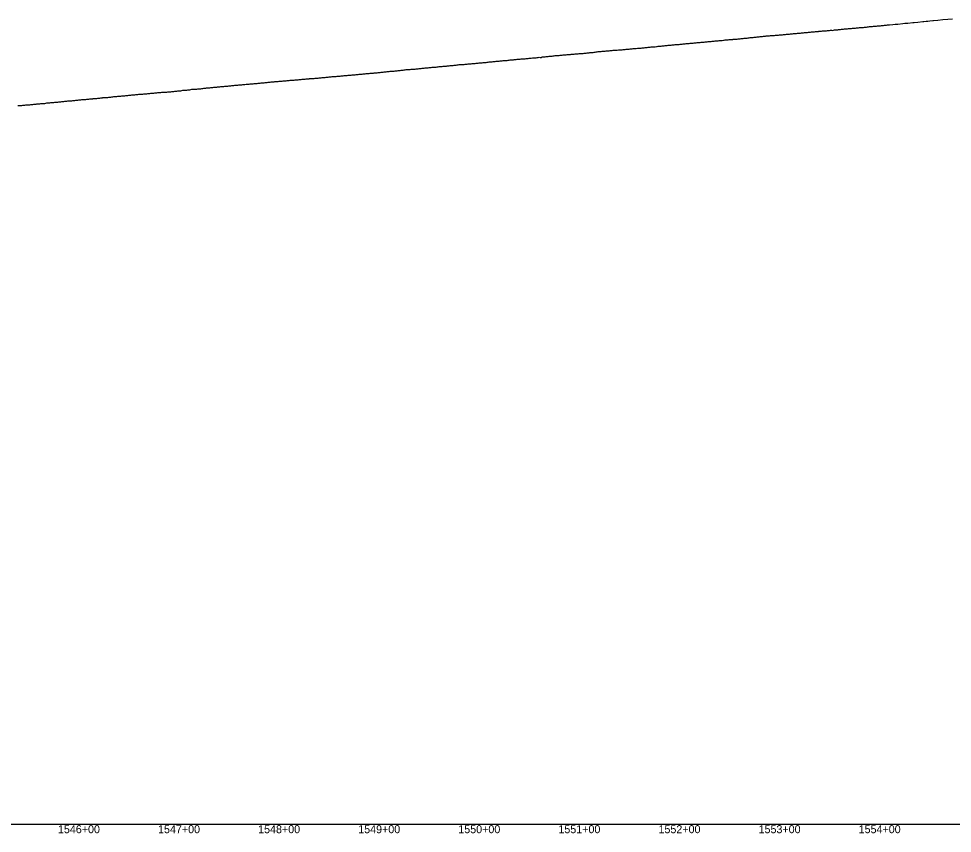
# Model space of a CAD drawing. Extents: x -3793 to 50787, y -1075 to 6138.
# Drawn here: x 41858 to 42791, y 2991 to 3805 of the extents above; entities that cross this region are included whole.
import ezdxf

# ---------------------------------------------------------------- set-up
doc = ezdxf.new("R2010")
doc.units = 0
for name, color, linetype in [('RD_DDB_Profile_EX', 7, 'Continuous'), ('RD_DDB_StaTX', 7, 'Continuous'), ('RD_GPK_Profile_Cell', 7, 'Continuous')]:
    doc.layers.add(name, color=color, linetype=linetype)

msp = doc.modelspace()

# ---------------------------------------------------------------- linework, layer by layer
at = {"layer": 'RD_DDB_Profile_EX'}
for points in [[(42639.398531, 3790.06941), (42640.398902, 3790.3162), (42641.389983, 3790.3676), (42642.390352, 3790.51824), (42643.39123, 3790.666715), (42644.391599, 3790.716415), (42645.391977, 3790.71897), (42646.392354, 3790.81863), (42647.393224, 3790.967175), (42648.3936, 3791.018735), (42649.393781, 3791.069245), (42650.394139, 3791.217005), (42651.394506, 3791.413995), (42652.395368, 3791.466995), (42653.385912, 3791.517495), (42654.386275, 3791.615375), (42655.386637, 3791.71417), (42656.386999, 3791.765445), (42657.387857, 3791.86498), (42657.80875, 3791.88586), (42658.388211, 3791.914575), (42659.388402, 3792.063355), (42660.388747, 3792.162935), (42661.389597, 3792.263995), (42662.389949, 3792.31356), (42663.390294, 3792.36457), (42664.390645, 3792.414085), (42665.390996, 3792.51292), (42666.391847, 3792.61254), (42667.382337, 3792.66212), (42668.38267, 3792.810975), (42669.383002, 3792.90988), (42670.38321, 3792.911195), (42671.384049, 3792.86386), (42672.384387, 3793.210345), (42673.384718, 3793.259285), (42674.385054, 3793.30933), (42675.38539, 3793.409315), (42676.386229, 3793.50957), (42676.882788, 3793.53412), (42677.386554, 3793.55994), (42678.386878, 3793.65928), (42679.387119, 3793.758615), (42680.378037, 3793.958005), (42681.378865, 3794.05776), (42682.379693, 3794.157935), (42683.380517, 3794.257655), (42684.381345, 3794.35828), (42685.382173, 3794.45799), (42686.419807, 3794.51328), (42687.383814, 3794.60923), (42688.384632, 3794.66033), (42689.385444, 3794.710455), (42690.376273, 3794.859105), (42691.37709, 3794.958705), (42692.377902, 3794.961915), (42693.378217, 3795.010625), (42694.379034, 3795.1593), (42695.379846, 3795.2104), (42695.956826, 3795.268125), (42696.380659, 3795.3105), (42697.381467, 3795.510055), (42698.382269, 3795.660105), (42699.383076, 3795.66016), (42700.383883, 3795.66124), (42701.3748, 3795.76133), (42702.375505, 3795.86139), (42703.376312, 3796.01041), (42704.377114, 3796.06203), (42705.493845, 3796.185265), (42706.37872, 3796.361035), (42707.379513, 3796.411015), (42708.380311, 3796.560475), (42709.381109, 3796.660465), (42710.381902, 3796.71044), (42711.372712, 3796.860985), (42712.37351, 3796.96045), (42713.374303, 3797.108865), (42714.374601, 3797.157675), (42715.030864, 3797.15767), (42715.375391, 3797.15955), (42716.376181, 3797.20994), (42717.376971, 3797.358915), (42718.377756, 3797.458365), (42719.378545, 3797.509675), (42720.369439, 3797.70871), (42721.370223, 3797.709075), (42722.370922, 3797.808995), (42723.371712, 3797.95936), (42724.567883, 3798.07877), (42725.373281, 3798.15912), (42726.374064, 3798.208965), (42727.374842, 3798.35838), (42728.406739, 3798.361955), (42731.771588, 3798.7585), (42734.104902, 3798.94505), (42736.765233, 3799.157925), (42741.768633, 3799.70673), (42743.641921, 3799.87542), (42746.762838, 3800.15652), (42751.756204, 3800.654475)], [(42751.756204, 3800.654475), (42753.178941, 3800.782005), (42756.75934, 3801.102695), (42761.75249, 3801.65084), (42762.71596, 3801.72766), (42765.040757, 3801.91286), (42766.758587, 3802.049645), (42768.608844, 3802.23539), (42771.752606, 3802.550805), (42772.252979, 3802.60109), (42776.749585, 3803.05263), (42781.789998, 3803.60834), (42786.753317, 3804.105235), (42791.327017, 3804.518305)], [(42543.411697, 3781.210655), (42544.412235, 3781.311575), (42545.412271, 3781.46052), (42546.412301, 3781.5101), (42547.412331, 3781.559675), (42548.412875, 3781.65996), (42549.412905, 3781.7601), (42550.412834, 3781.8602), (42551.412868, 3781.959215), (42552.413404, 3782.05951), (42552.90154, 3782.13251), (42553.413434, 3782.208535), (42554.413448, 3782.258055), (42555.413462, 3782.407575), (42556.413983, 3782.4578), (42557.413998, 3782.55732), (42558.414012, 3782.70684), (42559.41403, 3782.806365), (42560.404635, 3782.75738), (42561.404644, 3782.8572), (42562.438559, 3783.06171), (42563.405157, 3783.20547), (42564.40566, 3783.305275), (42565.40616, 3783.355415), (42566.406659, 3783.4063), (42567.407162, 3783.505705), (42568.407583, 3783.605455), (42569.408085, 3783.60719), (42570.408084, 3783.60773), (42571.408585, 3783.856425), (42571.975578, 3783.884855), (42572.409078, 3783.906565), (42573.409561, 3783.95667), (42574.410043, 3784.00678), (42575.410522, 3784.107285), (42576.401097, 3784.108245), (42577.401071, 3784.256795), (42578.401554, 3784.45614), (42579.402038, 3784.50663), (42580.402522, 3784.60634), (42581.512597, 3784.718615), (42582.403472, 3784.80771), (42583.403937, 3784.95695), (42584.403818, 3785.0563), (42585.404282, 3785.107095), (42586.404747, 3785.207145), (42587.405211, 3785.25682), (42588.405675, 3785.406875), (42589.406136, 3785.55692), (42590.406098, 3785.65623), (42591.049617, 3785.688425), (42591.406556, 3785.706955), (42592.397083, 3785.75697), (42593.39753, 3785.956955), (42594.397977, 3786.056595), (42595.398424, 3786.106585), (42596.398871, 3786.35588), (42597.398806, 3786.40578), (42598.399253, 3786.50577), (42599.399639, 3786.655455), (42600.586636, 3786.746115), (42601.40052, 3786.70598), (42602.40095, 3786.905015), (42603.40188, 3787.05597), (42604.402812, 3787.20627), (42605.393326, 3787.305855), (42606.394265, 3787.405645), (42607.395203, 3787.40704), (42608.395633, 3787.50654), (42609.396575, 3787.656625), (42610.397, 3787.65749), (42611.397926, 3787.708035), (42612.398846, 3787.808565), (42613.399159, 3787.85951), (42614.400072, 3788.008425), (42615.40099, 3788.058935), (42616.401405, 3788.16), (42617.392459, 3788.16184), (42618.393378, 3788.310505), (42619.660674, 3788.361195), (42620.394704, 3788.361565), (42621.395613, 3788.4635), (42622.396011, 3788.661895), (42623.39692, 3788.71241), (42624.397821, 3788.812155), (42625.398226, 3788.91199), (42626.398972, 3789.013245), (42627.399874, 3789.11457), (42628.400274, 3789.164375), (42629.401174, 3789.265735), (42630.392236, 3789.362835), (42631.392627, 3789.465995), (42632.393512, 3789.565625), (42633.394405, 3789.665215), (42634.394788, 3789.71585), (42635.395681, 3789.76724), (42636.396565, 3789.916805), (42637.396773, 3789.96748), (42638.397652, 3789.970815), (42638.734712, 3790.00469), (42639.398531, 3790.06941)], [(42447.435848, 3772.504305), (42447.994331, 3772.532315), (42448.436142, 3772.555145), (42449.436919, 3772.65629), (42450.437198, 3772.70645), (42451.437474, 3772.80619), (42452.437753, 3772.90634), (42453.438028, 3772.956485), (42454.438308, 3773.006635), (42455.439085, 3773.05788), (42456.439365, 3773.158545), (42457.53135, 3773.27249), (42458.439792, 3773.407785), (42459.430152, 3773.45789), (42460.430405, 3773.508525), (42461.431155, 3773.56159), (42462.43141, 3773.661725), (42463.431658, 3773.760665), (42464.431912, 3773.85959), (42465.43216, 3774.0109), (42466.432415, 3774.06041), (42467.068369, 3774.124465), (42467.433155, 3774.160525), (42468.433383, 3774.21124), (42469.433605, 3774.31129), (42470.433834, 3774.36268), (42471.434055, 3774.462065), (42472.434284, 3774.61145), (42473.435008, 3774.66219), (42474.435237, 3774.712245), (42475.435458, 3774.81157), (42476.605388, 3774.920115), (42477.435887, 3774.96308), (42478.43644, 3775.063045), (42479.436635, 3775.163035), (42480.436839, 3775.214565), (42481.427196, 3775.26534), (42482.4274, 3775.364575), (42483.427595, 3775.51456), (42484.428302, 3775.66372), (42485.428497, 3775.714515), (42486.428694, 3775.81611), (42487.428864, 3775.91523), (42488.429042, 3775.965165), (42489.429212, 3776.11509), (42490.429894, 3776.264965), (42491.430064, 3776.31572), (42492.430243, 3776.41648), (42493.430413, 3776.46558), (42494.430583, 3776.565505), (42495.679426, 3776.740645), (42496.421425, 3776.81695), (42497.42157, 3776.96512), (42498.421724, 3777.065), (42499.421869, 3777.11569), (42500.422518, 3777.21632), (42501.422672, 3777.362785), (42502.422817, 3777.46267), (42503.422971, 3777.514245), (42504.42362, 3777.66481), (42505.42376, 3777.76467), (42506.42389, 3777.81535), (42507.424011, 3777.96347), (42508.424635, 3778.014815), (42509.424765, 3778.11464), (42510.424716, 3778.214455), (42511.424839, 3778.26595), (42512.425467, 3778.36566), (42513.42559, 3778.4646), (42514.425721, 3778.61273), (42514.753464, 3778.64545), (42515.425829, 3778.71253), (42516.426425, 3778.71551), (42517.416713, 3778.71698), (42518.41681, 3778.866695), (42519.416907, 3779.014765), (42520.417518, 3779.16271), (42521.417615, 3779.21166), (42522.417712, 3779.313915), (42523.417817, 3779.41529), (42524.418417, 3779.51412), (42525.418491, 3779.613005), (42526.418573, 3779.76273), (42527.418648, 3779.763225), (42528.419075, 3779.864425), (42529.419153, 3779.96332), (42530.419231, 3779.96455), (42531.419316, 3779.964225), (42532.419891, 3780.113885), (42533.419969, 3780.262815), (42533.827502, 3780.283065), (42534.420042, 3780.31322), (42535.420097, 3780.462125), (42536.420652, 3780.563185), (42537.420715, 3780.613525), (42538.410919, 3780.66314), (42539.410978, 3780.812075), (42540.411536, 3780.961045), (42541.411588, 3781.012045), (42542.411646, 3781.11167), (42543.411697, 3781.210655)], [(42356.455189, 3763.951945), (42357.455268, 3764.001985), (42358.454832, 3764.05169), (42359.454911, 3764.151645), (42360.454476, 3764.25087), (42361.454555, 3764.300975), (42362.454109, 3764.300405), (42363.454153, 3764.400375), (42363.946038, 3764.424605), (42364.454343, 3764.44962), (42365.454401, 3764.599605), (42366.454463, 3764.699595), (42367.455284, 3764.848775), (42368.455346, 3764.998835), (42369.456165, 3765.09797), (42370.456227, 3765.198075), (42371.698178, 3765.272365), (42372.454061, 3765.34789), (42373.455783, 3765.44875), (42374.455917, 3765.448765), (42375.454322, 3765.54853), (42376.455426, 3765.699245), (42377.45556, 3765.79918), (42378.444594, 3765.9989), (42379.445064, 3765.899765), (42380.445199, 3765.89976), (42381.444849, 3766.2995), (42382.143434, 3766.36985), (42382.445106, 3766.400175), (42383.445083, 3766.45005), (42383.812663, 3766.48676), (42384.584561, 3766.563945), (42385.44555, 3766.650465), (42386.445527, 3766.75039), (42387.445504, 3766.90024), (42388.445994, 3767.000865), (42389.445971, 3767.05073), (42390.445948, 3767.100595), (42390.772216, 3767.1171), (42391.446415, 3767.15136), (42392.44636, 3767.40086), (42393.446816, 3767.45143), (42394.446761, 3767.601245), (42395.446706, 3767.70106), (42396.447161, 3767.701665), (42397.447106, 3767.80139), (42398.447051, 3767.901205), (42399.447506, 3768.001615), (42400.447446, 3767.951705), (42401.447345, 3768.05151), (42402.447762, 3768.301635), (42403.44768, 3768.351585), (42404.447596, 3768.451325), (42405.448014, 3768.55161), (42406.44793, 3768.65138), (42407.447847, 3768.80108), (42408.448265, 3768.80168), (42409.448181, 3768.801605), (42409.846254, 3768.86182), (42410.438099, 3768.951235), (42411.438492, 3769.051655), (42412.438374, 3769.05134), (42413.438257, 3769.200965), (42414.43865, 3769.25136), (42415.438532, 3769.300995), (42416.438415, 3769.350935), (42417.438807, 3769.451495), (42418.43869, 3769.700905), (42419.439081, 3769.751175), (42420.438934, 3769.80089), (42421.438786, 3769.90053), (42422.439148, 3769.901075), (42423.439001, 3770.10057), (42424.438854, 3770.20016), (42425.439216, 3770.150605), (42426.439069, 3770.400125), (42426.809814, 3770.43708), (42427.43905, 3770.49972), (42428.104581, 3770.53327), (42428.439284, 3770.550115), (42428.920293, 3770.598035), (42429.439278, 3770.649655), (42430.439338, 3770.79905), (42431.439511, 3770.79951), (42431.859744, 3770.84201), (42432.440119, 3770.9006), (42433.44045, 3771.050895), (42434.440782, 3771.15119), (42435.441113, 3771.251405), (42436.441444, 3771.451485), (42437.432317, 3771.602195), (42438.457312, 3771.60507), (42439.432917, 3771.70279), (42440.433219, 3771.852985), (42441.433522, 3772.002755), (42442.433826, 3772.003375), (42443.434632, 3772.004735), (42444.434937, 3772.10496), (42445.43524, 3772.25488), (42446.435545, 3772.35509), (42447.435848, 3772.504305)], [(42261.487296, 3754.958555), (42262.487251, 3755.058055), (42263.487704, 3755.257835), (42264.487655, 3755.35777), (42265.487611, 3755.407255), (42266.487562, 3755.408085), (42266.790969, 3755.423235), (42267.487485, 3755.458855), (42268.487395, 3755.6574), (42269.477396, 3755.70771), (42270.477814, 3755.80693), (42271.477723, 3755.95545), (42272.477636, 3756.00671), (42273.477545, 3756.107475), (42274.477454, 3756.15735), (42275.477362, 3756.257645), (42276.477269, 3756.406675), (42277.477137, 3756.555685), (42278.477515, 3756.65611), (42279.477387, 3756.706385), (42280.477254, 3756.756635), (42281.477122, 3756.85646), (42282.476915, 3756.957075), (42283.476785, 3757.106495), (42284.476654, 3757.15631), (42285.476524, 3757.206125), (42285.865007, 3757.22574), (42286.476876, 3757.256605), (42287.476706, 3757.356735), (42288.476536, 3757.456475), (42289.476369, 3757.655185), (42290.476199, 3757.70497), (42291.476029, 3757.85475), (42292.476363, 3757.9055), (42293.4767, 3758.05556), (42294.47653, 3758.1557), (42295.47686, 3758.20651), (42296.476655, 3758.256575), (42297.476948, 3758.456215), (42298.47674, 3758.60519), (42299.477037, 3758.60552), (42300.476828, 3758.6564), (42301.477122, 3758.806795), (42302.467502, 3758.857195), (42303.467294, 3758.906895), (42304.467592, 3758.95729), (42304.939045, 3759.004305), (42305.467359, 3759.05696), (42306.467622, 3759.1573), (42307.467371, 3759.355715), (42308.46763, 3759.406845), (42309.467888, 3759.50716), (42310.467642, 3759.55683), (42311.4679, 3759.657145), (42312.467649, 3759.75723), (42313.467912, 3759.857125), (42314.476064, 3759.907625), (42315.467882, 3760.007485), (42316.467598, 3760.10707), (42317.467818, 3760.10778), (42318.468037, 3760.258525), (42319.467749, 3760.35763), (42320.467973, 3760.40837), (42321.467685, 3760.40832), (42322.467905, 3760.706915), (42323.467621, 3760.756935), (42324.013083, 3760.784355), (42324.467828, 3760.80761), (42325.468011, 3760.90828), (42326.467608, 3761.05653), (42327.467792, 3761.15674), (42328.467476, 3761.25708), (42329.467656, 3761.30772), (42330.46734, 3761.456435), (42331.467525, 3761.55666), (42332.467208, 3761.656185), (42333.550102, 3761.764315), (42334.46754, 3761.85619), (42335.467187, 3762.005685), (42336.467336, 3761.95694), (42337.466979, 3762.15567), (42338.467128, 3762.205835), (42339.466774, 3762.35468), (42340.466923, 3762.35547), (42341.467068, 3762.50563), (42342.456778, 3762.605105), (42343.087121, 3762.668235), (42343.456915, 3762.70525), (42344.456519, 3762.705205), (42345.45663, 3762.75532), (42346.456234, 3762.904655), (42347.456348, 3763.05402), (42348.455951, 3763.15303), (42349.456063, 3763.30356), (42350.456177, 3763.35389), (42351.45578, 3763.4533), (42352.62414, 3763.56172), (42353.455465, 3763.60276), (42354.455544, 3763.702645), (42355.45511, 3763.852025), (42356.455189, 3763.951945)], [(42166.504283, 3746.10456), (42167.504175, 3746.204355), (42168.50402, 3746.303925), (42169.504424, 3746.404235), (42170.504319, 3746.504285), (42171.504206, 3746.60408), (42172.504562, 3746.704575), (42173.504405, 3746.75431), (42174.504251, 3746.80428), (42175.504604, 3746.905045), (42176.504447, 3747.00428), (42177.50429, 3747.10424), (42178.504641, 3747.204255), (42179.504484, 3747.20424), (42180.504837, 3747.354465), (42180.957797, 3747.42231), (42181.504652, 3747.503445), (42182.504448, 3747.504105), (42183.504752, 3747.60453), (42184.504546, 3747.803735), (42185.504343, 3747.85366), (42186.504647, 3747.90454), (42187.504441, 3747.954195), (42188.504238, 3748.05365), (42189.504542, 3748.104075), (42190.504336, 3748.203955), (42191.504086, 3748.30336), (42192.504343, 3748.403725), (42193.504094, 3748.40371), (42194.504348, 3748.45431), (42195.504099, 3748.60368), (42196.49388, 3748.653245), (42197.494139, 3748.753825), (42198.493886, 3748.953055), (42199.493633, 3748.95307), (42200.031835, 3749.007115), (42200.49387, 3749.053475), (42201.493571, 3749.252795), (42202.493272, 3749.352165), (42203.493485, 3749.40262), (42204.493186, 3749.5017), (42205.493376, 3749.601985), (42206.493082, 3749.65193), (42207.492789, 3749.65148), (42208.492999, 3749.901425), (42209.568854, 3749.95876), (42210.492372, 3750.050625), (42211.492538, 3750.10093), (42212.4922, 3750.20034), (42213.073745, 3750.258175), (42213.492224, 3750.299765), (42214.542514, 3750.4), (42215.492505, 3750.399495), (42215.982077, 3750.47351), (42216.492359, 3750.550555), (42217.492525, 3750.600855), (42218.49269, 3750.70113), (42219.105873, 3750.76261), (42219.492838, 3750.80138), (42220.49296, 3751.00136), (42221.493081, 3751.15145), (42222.493202, 3751.201805), (42223.493325, 3751.302095), (42224.493947, 3751.35311), (42225.494068, 3751.50314), (42226.494191, 3751.603325), (42227.494313, 3751.65351), (42228.642892, 3751.783605), (42229.49452, 3751.953625), (42230.494598, 3752.05374), (42231.494678, 3752.05407), (42232.495257, 3752.204705), (42233.485387, 3752.25562), (42234.485469, 3752.355485), (42235.485549, 3752.45561), (42236.485628, 3752.556025), (42237.48571, 3752.705575), (42238.485776, 3752.70657), (42239.485812, 3752.80663), (42240.486359, 3753.00691), (42241.486395, 3753.107315), (42242.486431, 3753.207025), (42243.48647, 3753.307445), (42244.486506, 3753.407505), (42245.48647, 3753.606485), (42246.486508, 3753.606905), (42247.71693, 3753.681555), (42248.487047, 3753.758555), (42249.487044, 3753.80855), (42250.487037, 3753.957725), (42251.487029, 3754.107715), (42252.487026, 3754.15771), (42253.487019, 3754.208105), (42254.487012, 3754.258495), (42255.48751, 3754.45891), (42256.487503, 3754.45934), (42257.487486, 3754.55887), (42258.487438, 3754.659225), (42259.487393, 3754.80915), (42260.487345, 3754.859065), (42261.487296, 3754.958555)], [(42071.530454, 3737.693085), (42072.530157, 3737.793285), (42073.530602, 3737.892555), (42074.531047, 3737.99247), (42075.531486, 3738.09207), (42076.050587, 3738.117805), (42076.531955, 3738.14201), (42077.531708, 3738.14352), (42078.532202, 3738.34236), (42079.522788, 3738.39231), (42080.52328, 3738.49147), (42081.52303, 3738.59188), (42082.523529, 3738.64144), (42083.524028, 3738.790545), (42084.524526, 3738.93961), (42085.587606, 3739.04004), (42086.524816, 3739.04094), (42087.525366, 3739.090955), (42088.525916, 3739.23944), (42089.525616, 3739.38875), (42090.526153, 3739.43927), (42091.526697, 3739.538195), (42092.526503, 3739.589095), (42093.526309, 3739.640485), (42094.526854, 3739.73947), (42095.124625, 3739.82935), (42095.526664, 3739.889245), (42096.526513, 3739.939515), (42097.526361, 3739.9903), (42098.52621, 3740.090065), (42099.526058, 3740.191305), (42100.525907, 3740.340145), (42101.525755, 3740.43861), (42102.526337, 3740.539835), (42103.526186, 3740.59012), (42104.661645, 3740.75401), (42105.525928, 3740.84063), (42106.525829, 3740.94128), (42107.525729, 3741.091055), (42108.52563, 3741.19127), (42109.525524, 3741.191895), (42110.526164, 3741.29081), (42111.526065, 3741.34145), (42112.525965, 3741.49123), (42113.525866, 3741.591035), (42114.198664, 3741.62483), (42114.525784, 3741.64163), (42115.515823, 3741.741365), (42116.515769, 3741.79113), (42117.515721, 3741.89204), (42118.515673, 3741.94255), (42119.516371, 3741.99183), (42120.516323, 3742.041155), (42121.516274, 3742.23972), (42122.516226, 3742.341055), (42123.735683, 3742.4026), (42124.516166, 3742.442055), (42125.516171, 3742.591365), (42126.516176, 3742.641435), (42127.516927, 3742.74094), (42128.516932, 3742.889775), (42129.516192, 3742.991275), (42130.51612, 3743.04171), (42131.515388, 3743.092755), (42132.515394, 3743.143135), (42133.514674, 3743.244115), (42134.514733, 3743.29464), (42135.514052, 3743.395475), (42136.514114, 3743.54478), (42137.513431, 3743.59593), (42138.513491, 3743.69592), (42139.512806, 3743.796845), (42140.512866, 3743.84683), (42141.51218, 3743.947655), (42142.809721, 3743.992565), (42143.512337, 3744.097785), (42144.511705, 3744.24853), (42145.511818, 3744.298505), (42146.511185, 3744.34929), (42147.511299, 3744.44916), (42148.51073, 3744.55004), (42149.045968, 3744.630285), (42149.561005, 3744.702515), (42150.511223, 3744.750645), (42151.511214, 3744.750605), (42152.511708, 3744.80138), (42153.511649, 3744.90123), (42154.512101, 3745.05182), (42155.502056, 3745.151585), (42156.502514, 3745.2022), (42157.502455, 3745.252295), (42158.502914, 3745.352685), (42159.502854, 3745.452545), (42160.503313, 3745.553515), (42161.503255, 3745.65303), (42161.883759, 3745.63425), (42162.503681, 3745.60441), (42163.503573, 3745.75398), (42164.503983, 3745.904185), (42165.503873, 3746.003975), (42166.504283, 3746.10456)], [(41975.403936, 3728.70806), (41976.404167, 3728.658805), (41977.404396, 3728.956395), (41978.404627, 3729.057095), (41979.404856, 3729.10734), (41980.680397, 3729.15704), (41981.405457, 3729.15862), (41982.40568, 3729.15983), (41983.405902, 3729.408575), (41984.406271, 3729.458105), (41985.406495, 3729.55783), (41986.406717, 3729.60854), (41987.40694, 3729.70927), (41988.407308, 3729.759755), (41989.407531, 3729.810505), (41990.407752, 3729.95974), (41991.407969, 3730.109395), (41992.408184, 3730.11063), (41993.408446, 3730.259005), (41994.40866, 3730.35918), (41995.408875, 3730.408825), (41996.409088, 3730.55899), (41997.409456, 3730.706965), (41998.409671, 3730.75912), (41999.409885, 3730.85878), (41999.754435, 3730.87606), (42000.410097, 3730.909945), (42001.410305, 3731.00953), (42002.410667, 3731.009405), (42003.410875, 3731.20852), (42004.401187, 3731.25911), (42005.549184, 3731.110655), (42006.549496, 3731.20982), (42007.549803, 3731.309445), (42008.550116, 3731.45957), (42009.549822, 3731.509375), (42010.550075, 3731.60944), (42011.550323, 3731.808545), (42012.550086, 3731.858305), (42013.550338, 3731.85969), (42014.550586, 3731.95975), (42015.550839, 3732.10893), (42016.550601, 3732.208585), (42017.550853, 3732.30824), (42018.828473, 3732.451795), (42019.541382, 3732.55829), (42020.541077, 3732.60784), (42021.54127, 3732.757465), (42022.541461, 3732.956335), (42023.541654, 3733.05633), (42024.541347, 3733.155955), (42025.541537, 3733.256275), (42026.541731, 3733.25693), (42027.541422, 3733.355485), (42028.541605, 3733.455755), (42029.541737, 3733.406805), (42030.541816, 3733.75476), (42031.541456, 3733.95329), (42032.541591, 3734.003925), (42033.541724, 3734.054085), (42034.531892, 3734.10378), (42035.531522, 3734.15301), (42036.531654, 3734.25329), (42037.531787, 3734.353385), (42037.902511, 3734.37189), (42038.531883, 3734.4031), (42039.531454, 3734.5024), (42040.531528, 3734.60214), (42041.531604, 3734.80169), (42042.531677, 3734.80184), (42043.531246, 3735.000775), (42044.53132, 3735.05071), (42045.531394, 3735.200505), (42046.103633, 3735.314495), (42046.531597, 3735.39952), (42047.531902, 3735.44937), (42048.532251, 3735.449175), (42049.5326, 3735.549), (42050.533699, 3735.647965), (42051.534046, 3735.79763), (42052.534395, 3735.89753), (42053.534741, 3735.99732), (42054.525887, 3736.096075), (42055.526234, 3736.19606), (42056.526585, 3736.24497), (42056.976549, 3736.289835), (42057.526959, 3736.344435), (42058.527358, 3736.44531), (42059.527753, 3736.59477), (42060.527354, 3736.645325), (42061.527747, 3736.695035), (42062.528143, 3736.74526), (42063.528535, 3736.89472), (42064.528188, 3736.994745), (42065.52858, 3737.14391), (42066.528977, 3737.194125), (42067.529421, 3737.244035), (42068.529124, 3737.344245), (42069.529569, 3737.493855), (42070.530009, 3737.59285), (42071.530454, 3737.693085)], [(41881.417061, 3719.754195), (41882.417549, 3719.85461), (41883.418038, 3719.9548), (41884.418527, 3719.95524), (41885.419162, 3720.203685), (41886.419636, 3720.304025), (41887.420111, 3720.40413), (41888.420585, 3720.454235), (41889.411111, 3720.604315), (41890.411586, 3720.704425), (41891.412062, 3720.7548), (41892.412677, 3720.85394), (41893.413153, 3720.95381), (41894.413627, 3721.053915), (41894.847225, 3721.05396), (41895.414095, 3721.05498), (41896.414506, 3721.15504), (41897.414966, 3721.25484), (41898.415426, 3721.305415), (41899.415887, 3721.454955), (41900.416496, 3721.554225), (41901.416957, 3721.753605), (41902.417417, 3721.853195), (41903.417877, 3721.95347), (41904.418338, 3722.054215), (41905.408832, 3722.10395), (41906.40928, 3722.1544), (41907.409867, 3722.35304), (41908.410315, 3722.45284), (41909.410763, 3722.55321), (41910.411211, 3722.553765), (41911.411658, 3722.603755), (41912.412105, 3722.70356), (41913.412516, 3722.90299), (41913.921263, 3722.92841), (41914.412958, 3722.953135), (41915.413543, 3723.052225), (41916.413978, 3723.201755), (41917.414414, 3723.20236), (41918.41485, 3723.30203), (41919.415286, 3723.451845), (41920.405745, 3723.502005), (41921.40618, 3723.651935), (41922.406615, 3723.652085), (41923.458282, 3723.70632), (41924.407615, 3723.80102), (41925.408038, 3723.950885), (41926.408461, 3724.05071), (41927.408884, 3724.15058), (41928.409307, 3724.25048), (41929.40973, 3724.350325), (41929.797899, 3724.388795), (41930.410484, 3724.449365), (41931.410954, 3724.49925), (41932.411425, 3724.599095), (41932.995302, 3724.65737), (41933.411899, 3724.69892), (41934.41238, 3724.7487), (41935.402884, 3724.798455), (41936.403368, 3724.89842), (41937.403852, 3725.048015), (41938.403923, 3725.0987), (41939.403993, 3725.19932), (41940.404476, 3725.39892), (41941.404542, 3725.54952), (41941.998757, 3725.609415), (41942.532321, 3725.65023), (41943.404958, 3725.65056), (41944.405218, 3725.70114), (41945.405619, 3725.751), (41946.405879, 3725.851435), (41947.406118, 3725.951815), (41948.406372, 3726.002675), (41949.406776, 3726.102145), (41950.407031, 3726.20263), (41951.407286, 3726.303115), (41952.06934, 3726.369625), (41952.407538, 3726.40358), (41953.407784, 3726.65311), (41954.408178, 3726.65327), (41955.408424, 3726.803415), (41956.40867, 3726.903515), (41957.408916, 3727.004115), (41958.40931, 3727.153335), (41959.409557, 3727.203635), (41960.409803, 3727.204545), (41961.606359, 3727.32446), (41962.410437, 3727.405195), (41963.410675, 3727.555205), (41964.410844, 3727.605865), (41965.411078, 3727.80547), (41966.411313, 3727.85653), (41967.411702, 3727.956175), (41968.411935, 3728.05613), (41969.402251, 3728.10763), (41970.402488, 3728.207585), (41971.402871, 3728.306795), (41972.403101, 3728.40707), (41973.40333, 3728.506915), (41974.403561, 3728.606725), (41975.403936, 3728.70806)], [(41857.424482, 3717.65057), (41858.415009, 3717.7508), (41859.415531, 3717.80121), (41860.416053, 3717.90153), (41861.416575, 3717.951845), (41862.417238, 3718.05123), (41863.41776, 3718.051785), (41864.418283, 3718.3018), (41865.418805, 3718.40184), (41866.419324, 3718.45194), (41867.41983, 3718.55258), (41868.420303, 3718.5533), (41869.420806, 3718.603565), (41870.421458, 3718.703005), (41871.421962, 3718.902775), (41872.422465, 3718.903355), (41873.422969, 3719.053415), (41874.413512, 3719.10383), (41875.414018, 3719.20408), (41875.773187, 3719.24007), (41876.414514, 3719.30406), (41877.415145, 3719.35369), (41878.415635, 3719.40408), (41879.416126, 3719.55427), (41880.416617, 3719.654245), (41881.417061, 3719.754195)]]:
    msp.add_lwpolyline(points, dxfattribs=at)
at = {"layer": 'RD_GPK_Profile_Cell'}
msp.add_line((1000, 3000), (46549.603806, 3000), dxfattribs=at)

# ---------------------------------------------------------------- texts
at = {"layer": 'RD_DDB_StaTX'}
for s, p in [('1546+00', (41897.651676, 2991)), ('1547+00', (41997.651676, 2991)), ('1548+00', (42097.651676, 2991)), ('1549+00', (42197.651676, 2991)), ('1550+00', (42297.651676, 2991)), ('1551+00', (42397.651676, 2991)), ('1552+00', (42497.651676, 2991)), ('1553+00', (42597.651676, 2991)), ('1554+00', (42697.651676, 2991))]:
    msp.add_text(s, height=8, dxfattribs=at).set_placement(p)

doc.saveas('drawing.dxf')
